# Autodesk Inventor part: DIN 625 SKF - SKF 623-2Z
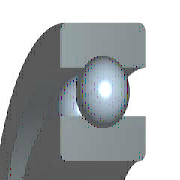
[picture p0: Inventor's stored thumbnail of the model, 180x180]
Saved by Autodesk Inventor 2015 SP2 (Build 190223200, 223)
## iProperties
Created: 2014-02
Part Number: DIN 625 SKF - SKF 623-2Z
Material: Stahl, weich
Description: Rillenkugellager, einreihig, beidseitig abgedeckt SKF
Document SubType Name: Modeling
Standard: DIN 625 SKF
Designer: ryll
Standards Organization: DIN
Language: de-DE
Size Designation: SKF 623-2Z
Categories: <MemberInstance><Categories><Category DisplayName="Wellenteile" InternalName="7f7aeb1f-a693-4053-b835-cee3144e0d98" Mnemonic="SHFT"><Category DisplayName="Lager
Density: 7.85 g/cm^3
Appearance: Halbpoliert
IsCustomPart: 0
Author: ryll
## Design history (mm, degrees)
node "WorkPoint1"
revolve "Drehung1" stored, may be unused: angle "d6" = 360 deg
node "WorkAxis1"
node "WorkPlane3"
revolve "Drehung2" stored, may be unused: angle "d10" = 360 deg
node "WorkPlane4"
node "WorkPoint2"
sketch "Skizze5"
  geometry: L1 (3.25, 0.95)-(3.25, 3.05); L2 (3.88, 0)-(-3.88, 0) reference; L3 (3.25, 0.95)-(3.25, 3.05); A1 r 1.05 centre (3.25, 2) between (3.25, 0.95) and (3.25, 3.05); A2 r 1.05 centre (3.25, 2) between (3.88, 1.16) and (3.88, 2.84) reference
  constraints: 4 end point, 2 point on circle, 1 centre point, 1 concentric, 1 vertical
  dimensions: "d13" = 0 horizontal distance of A1.centre L1.start; "d15" = 2.1001 diameter of A1 (computed from msp_mdtd6)
revolve "Drehung3" sketch "Skizze5" stored, may be unused: angle "d16" = 360 deg
pattern_circular "Polare Anordnung1" dims "d17" = 50.42857 (= msp_pocet), angle "d19" = 360 deg
body "Solid1"
node "Skizze1"
node "Skizze4"
fillet "Rundung1" dims "d20" = 0.15 (= r)
sketch "Skizze2"
  geometry: L1 (1.5, 4)-(5, 4); L2 (1.5, 0)-(1.5, 4); L3 (5, 0)-(1.5, 0); L4 (5, 4)-(5, 0); L5 (0, 0)-(0, 20); L6 (0, 0)-(0, 20); L7 (-7.2, 0)-(43.2, 0) reference
  constraints: 12 end point, 3 vertical, 2 horizontal, 1 collinear, 1 other
  dimensions: "d1" = 3 diameter of L1.start L5 (= Diam); "d3" = 10 diameter of L1.end L5 (= DD); "d5" = 4 distance of L2.start L1.start (= msp_mdtd2)
sketch "Skizze3"
  geometry: L1 (3.88, 4)-(3.88, 2.84); L2 (2.62, 4)-(3.88, 4); L3 (2.62, 2.84)-(2.62, 4); L4 (2.62, 0)-(2.62, 1.16); L5 (3.88, 0)-(2.62, 0); L6 (3.88, 1.16)-(3.88, 0); L7 (5, 0)-(-5, 0) reference; L8 (5, 4)-(-5, 4) reference; L9 (0, -42.29)-(0, 61.29); L10 (0, 82.007)-(0, -63.007) reference; A1 r 1.05 centre (3.25, 2) between (3.88, 1.16) and (3.88, 2.84); A2 r 1.05 centre (3.25, 2) between (2.62, 2.84) and (2.62, 1.16)
  constraints: 14 end point, 4 collinear, 4 point on circle, 4 vertical, 2 centre point, 2 concentric, 2 horizontal, 2 point on line
  dimensions: "d9" = 2.1 diameter of A1 (= msp_mdtd6); "d21" = 2.62 distance between parallel lines of L9 L4 (= 0.5 x msp_d1); "d22" = 3.25 distance from line of L9 A1.centre (= 0.5 x msp_ds); "d23" = 3.88 distance between parallel lines of L9 L6 (= 0.5 x msp_dd1)
other parameters: "Diam" = 3 [user parameter; used in 3 equation terms], "DD" = 10 [user parameter; used in 3 equation terms], "B" = 4 [user parameter; used in 1 equation term], "r" = 0.15 [user parameter; used in 1 equation term], "msp_ds" = 6.5 (= 0.5 x Diam + 0.5 x DD) [user parameter; used in 5 equation terms], "msp_d0" = 2.1 (= -0.3 x Diam + 0.3 x DD) [user parameter; used in 4 equation terms], "msp_d1" = 5.24 (= msp_ds - 0.6 x msp_d0) [user parameter; used in 1 equation term], "msp_dd1" = 7.76 (= msp_ds + 0.6 x msp_d0) [user parameter; used in 1 equation term], "msp_pom" = 9.75 (= 1.5 x msp_ds) [user parameter; used in 1 equation term], "msp_mdtd2" = 4 (= B) [user parameter; used in 3 equation terms], "msp_mdtd4" = 6.5 (= msp_ds) [user parameter], "msp_mdtd6" = 2.1 (= msp_d0) [user parameter; used in 2 equation terms], "msp_mdtd7" = 2 (= 0.5 x msp_mdtd2) [user parameter], "msp_pocet" = 50.42857 (computed from msp_d0, msp_pom) [user parameter; used in 1 equation term], "d2" = 72 (derived), "d4" = 19 (derived), "d7" = 0, "d8" = 15.6 (derived), "d11" = -4 (computed from msp_mdtd2), "d12" = 0 (derived), "d14" = 15.6001 (derived), "d26" = 0, "d27" = 0, "d28" = 0, "d29" = 0, "d30" = 0
